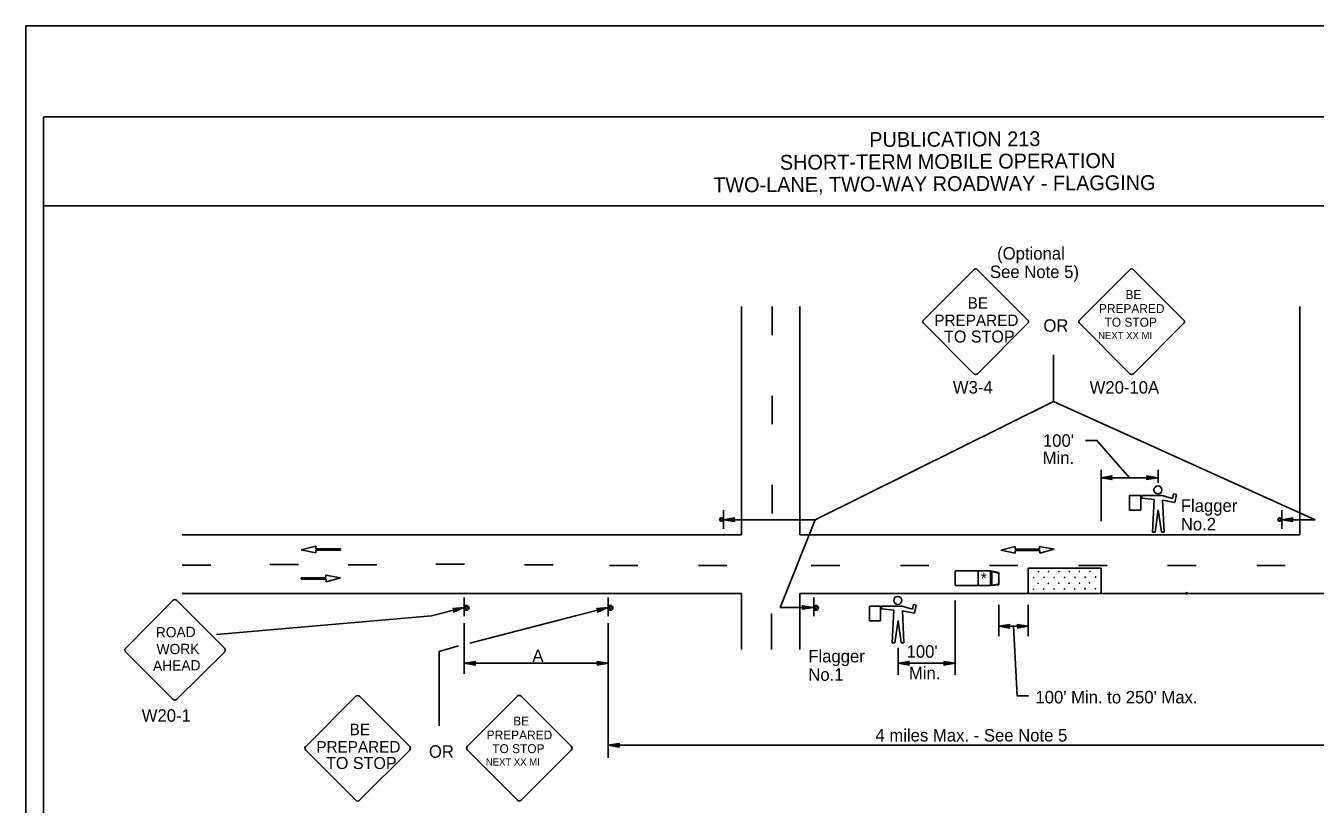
# Model space of a CAD drawing. Extents: x -14145 to -13662, y 30244 to 30661.
# Drawn here: x -13926.17 to -13904.46, y 30464.2 to 30477.31 of the extents above; entities that cross this region are included whole.
import ezdxf

# ---------------------------------------------------------------- set-up
doc = ezdxf.new("R2010")
doc.units = 0
for name, color, linetype in [('1', 7, 'Continuous'), ('10', 7, 'Continuous'), ('2', 7, 'Continuous'), ('4', 7, 'Continuous'), ('61', 7, 'Continuous')]:
    doc.layers.add(name, color=color, linetype=linetype)

msp = doc.modelspace()

# ---------------------------------------------------------------- linework, layer by layer
at = {"layer": '1'}
for p, q in [((-13914.122, 30468.737), (-13914.122, 30472.58)), ((-13913.606, 30472.58), (-13913.606, 30472.1)), ((-13913.138, 30468.737), (-13913.138, 30472.58)), ((-13904.722, 30468.737), (-13904.722, 30472.58)), ((-13908.87, 30471.769), (-13908.87, 30470.985)), ((-13913.606, 30471.08), (-13913.606, 30470.6)), ((-13912.882, 30468.993), (-13908.87, 30470.985)), ((-13904.461, 30468.993), (-13908.87, 30470.985)), ((-13908.068, 30468.97), (-13908.068, 30469.83)), ((-13907.108, 30469.611), (-13907.108, 30469.83)), ((-13908.068, 30469.7), (-13907.108, 30469.7)), ((-13913.606, 30469.58), (-13913.606, 30469.1)), ((-13907.399, 30469.401), (-13907.587, 30469.401)), ((-13907.587, 30469.401), (-13907.587, 30469.151)), ((-13907.399, 30469.151), (-13907.399, 30469.401)), ((-13907.041, 30469.401), (-13907.381, 30469.401)), ((-13907.381, 30469.401), (-13907.381, 30469.357)), ((-13906.863, 30469.349), (-13907.041, 30469.401)), ((-13906.845, 30469.429), (-13906.863, 30469.349)), ((-13906.797, 30469.417), (-13906.845, 30469.429)), ((-13906.827, 30469.283), (-13906.797, 30469.417)), ((-13907.381, 30469.357), (-13907.175, 30469.331)), ((-13907.175, 30469.331), (-13907.203, 30468.785)), ((-13907.006, 30468.785), (-13907.032, 30469.321)), ((-13907.032, 30469.321), (-13906.827, 30469.283)), ((-13914.424, 30469.155), (-13914.424, 30468.837)), ((-13912.882, 30468.993), (-13914.424, 30468.993)), ((-13913.473, 30467.515), (-13912.882, 30468.993)), ((-13907.587, 30469.151), (-13907.399, 30469.151)), ((-13907.158, 30468.785), (-13907.104, 30469.159)), ((-13907.104, 30469.159), (-13907.051, 30468.785)), ((-13905.024, 30469.155), (-13905.024, 30468.837)), ((-13904.461, 30468.993), (-13905.024, 30468.993)), ((-13907.203, 30468.785), (-13907.158, 30468.785)), ((-13907.051, 30468.785), (-13907.006, 30468.785)), ((-13923.54, 30468.737), (-13914.122, 30468.737)), ((-13921.292, 30468.549), (-13921.534, 30468.483)), ((-13921.292, 30468.504), (-13921.292, 30468.549)), ((-13913.138, 30468.737), (-13904.722, 30468.737)), ((-13909.516, 30468.544), (-13909.757, 30468.478)), ((-13909.516, 30468.499), (-13909.516, 30468.544)), ((-13908.858, 30468.498), (-13909.102, 30468.544)), ((-13909.102, 30468.544), (-13909.102, 30468.499)), ((-13921.534, 30468.483), (-13921.29, 30468.436)), ((-13920.876, 30468.504), (-13921.292, 30468.504)), ((-13921.29, 30468.436), (-13921.29, 30468.482)), ((-13921.29, 30468.482), (-13920.876, 30468.482)), ((-13920.876, 30468.482), (-13920.876, 30468.504)), ((-13909.757, 30468.478), (-13909.513, 30468.432)), ((-13909.102, 30468.499), (-13909.516, 30468.499)), ((-13909.513, 30468.477), (-13909.099, 30468.477)), ((-13909.513, 30468.432), (-13909.513, 30468.477)), ((-13909.099, 30468.432), (-13908.858, 30468.498)), ((-13909.099, 30468.477), (-13909.099, 30468.432)), ((-13923.06, 30468.227), (-13923.54, 30468.227)), ((-13921.584, 30468.239), (-13922.064, 30468.239)), ((-13920.264, 30468.233), (-13920.744, 30468.233)), ((-13918.788, 30468.245), (-13919.268, 30468.245)), ((-13917.294, 30468.233), (-13917.774, 30468.233)), ((-13915.866, 30468.221), (-13916.346, 30468.221)), ((-13914.366, 30468.221), (-13914.846, 30468.221)), ((-13912.466, 30468.221), (-13912.946, 30468.221)), ((-13910.966, 30468.221), (-13911.446, 30468.221)), ((-13910.522, 30467.885), (-13910.522, 30468.131)), ((-13909.928, 30468.131), (-13910.522, 30468.131)), ((-13910.138, 30467.885), (-13910.138, 30468.131)), ((-13909.466, 30468.221), (-13909.946, 30468.221)), ((-13909.928, 30467.885), (-13909.928, 30468.131)), ((-13909.928, 30468.131), (-13909.79, 30468.107)), ((-13909.904, 30468.125), (-13909.79, 30468.089)), ((-13909.904, 30467.885), (-13909.904, 30468.125)), ((-13909.79, 30467.897), (-13909.79, 30468.107)), ((-13908.068, 30468.179), (-13909.292, 30468.179)), ((-13909.292, 30467.753), (-13909.292, 30468.179)), ((-13907.966, 30468.221), (-13908.446, 30468.221)), ((-13908.068, 30467.753), (-13908.068, 30468.179)), ((-13906.466, 30468.221), (-13906.946, 30468.221)), ((-13904.966, 30468.221), (-13905.446, 30468.221)), ((-13921.12, 30468.013), (-13921.534, 30468.013)), ((-13921.534, 30468.013), (-13921.534, 30467.991)), ((-13921.534, 30467.991), (-13921.117, 30467.991)), ((-13920.876, 30468.012), (-13921.12, 30468.058)), ((-13921.12, 30468.058), (-13921.12, 30468.013)), ((-13921.117, 30467.946), (-13920.876, 30468.012)), ((-13921.117, 30467.991), (-13921.117, 30467.946)), ((-13909.928, 30467.885), (-13910.522, 30467.885)), ((-13909.928, 30467.885), (-13909.79, 30467.897)), ((-13909.904, 30467.885), (-13909.79, 30467.915)), ((-13923.54, 30467.753), (-13914.122, 30467.753)), ((-13918.79, 30467.682), (-13918.79, 30467.37)), ((-13916.366, 30467.682), (-13916.366, 30467.37)), ((-13914.122, 30466.808), (-13914.122, 30467.753)), ((-13913.138, 30466.808), (-13913.138, 30467.753)), ((-13913.138, 30467.753), (-13897.552, 30467.753)), ((-13912.903, 30467.682), (-13912.903, 30467.37)), ((-13923.696, 30467.635), (-13924.491, 30466.832)), ((-13922.827, 30466.832), (-13923.63, 30467.635)), ((-13919.343, 30467.375), (-13918.796, 30467.515)), ((-13916.919, 30467.375), (-13916.372, 30467.515)), ((-13913.473, 30467.515), (-13912.909, 30467.515)), ((-13911.78, 30467.539), (-13911.968, 30467.539)), ((-13911.968, 30467.539), (-13911.968, 30467.289)), ((-13911.78, 30467.289), (-13911.78, 30467.539)), ((-13911.422, 30467.539), (-13911.762, 30467.539)), ((-13911.762, 30467.539), (-13911.762, 30467.495)), ((-13911.762, 30467.495), (-13911.556, 30467.469)), ((-13911.556, 30467.469), (-13911.584, 30466.923)), ((-13911.244, 30467.487), (-13911.422, 30467.539)), ((-13911.387, 30466.923), (-13911.413, 30467.459)), ((-13911.413, 30467.459), (-13911.208, 30467.421)), ((-13911.226, 30467.567), (-13911.244, 30467.487)), ((-13911.178, 30467.555), (-13911.226, 30467.567)), ((-13911.208, 30467.421), (-13911.178, 30467.555)), ((-13910.522, 30466.379), (-13910.522, 30467.635)), ((-13909.79, 30467.03), (-13909.79, 30467.559)), ((-13909.292, 30467.03), (-13909.292, 30467.559)), ((-13922.961, 30467.058), (-13919.343, 30467.375)), ((-13918.79, 30466.397), (-13918.79, 30467.253)), ((-13918.697, 30466.912), (-13916.919, 30467.375)), ((-13916.366, 30464.985), (-13916.366, 30467.253)), ((-13913.618, 30467.413), (-13913.618, 30466.808)), ((-13911.968, 30467.289), (-13911.78, 30467.289)), ((-13911.539, 30466.923), (-13911.485, 30467.297)), ((-13911.485, 30467.297), (-13911.432, 30466.923)), ((-13909.292, 30467.199), (-13909.79, 30467.199)), ((-13919.21, 30466.774), (-13918.887, 30466.868)), ((-13911.584, 30466.923), (-13911.539, 30466.923)), ((-13911.482, 30466.379), (-13911.482, 30466.834)), ((-13911.432, 30466.923), (-13911.387, 30466.923)), ((-13924.491, 30466.766), (-13923.696, 30465.971)), ((-13923.63, 30465.971), (-13922.827, 30466.766)), ((-13919.21, 30465.522), (-13919.21, 30466.774)), ((-13916.366, 30466.577), (-13918.79, 30466.577)), ((-13911.482, 30466.577), (-13910.522, 30466.577)), ((-13902.224, 30465.195), (-13916.366, 30465.195))]:
    msp.add_line(p, q, dxfattribs=at)
for points in [[(-13911.053, 30472.358), (-13910.212, 30473.2)], [(-13910.146, 30473.2), (-13909.304, 30472.358)], [(-13908.427, 30472.358), (-13907.585, 30473.2)], [(-13907.52, 30473.2), (-13906.677, 30472.358)], [(-13910.212, 30471.45), (-13911.053, 30472.293)], [(-13909.304, 30472.293), (-13910.146, 30471.45)], [(-13907.585, 30471.45), (-13908.427, 30472.293)], [(-13906.677, 30472.293), (-13907.52, 30471.45)], [(-13908.33, 30470.327), (-13908.138, 30470.327), (-13907.588, 30469.7)], [(-13907.894, 30469.676), (-13907.9, 30469.694), (-13908.068, 30469.7), (-13907.894, 30469.676), (-13907.882, 30469.67), (-13908.068, 30469.7), (-13907.9, 30469.712), (-13907.894, 30469.724), (-13908.068, 30469.7), (-13907.882, 30469.73), (-13907.894, 30469.724)], [(-13907.288, 30469.724), (-13907.282, 30469.712), (-13907.108, 30469.7), (-13907.288, 30469.724), (-13907.3, 30469.73), (-13907.108, 30469.7), (-13907.282, 30469.694), (-13907.288, 30469.682), (-13907.108, 30469.7), (-13907.3, 30469.67), (-13907.288, 30469.682)], [(-13914.244, 30468.969), (-13914.25, 30468.981), (-13914.424, 30468.993), (-13914.244, 30468.969), (-13914.238, 30468.963), (-13914.424, 30468.993), (-13914.25, 30468.999), (-13914.244, 30469.011), (-13914.424, 30468.993), (-13914.238, 30469.023), (-13914.244, 30469.011)], [(-13904.844, 30468.969), (-13904.85, 30468.981), (-13905.024, 30468.993), (-13904.844, 30468.969), (-13904.838, 30468.963), (-13905.024, 30468.993), (-13904.85, 30468.999), (-13904.844, 30469.011), (-13905.024, 30468.993), (-13904.838, 30469.023), (-13904.844, 30469.011)], [(-13918.976, 30467.491), (-13918.964, 30467.479), (-13918.796, 30467.515), (-13918.976, 30467.491), (-13918.982, 30467.497), (-13918.796, 30467.515), (-13918.958, 30467.461), (-13918.964, 30467.449), (-13918.796, 30467.515), (-13918.97, 30467.437), (-13918.964, 30467.449)], [(-13916.552, 30467.491), (-13916.54, 30467.479), (-13916.372, 30467.515), (-13916.552, 30467.491), (-13916.558, 30467.497), (-13916.372, 30467.515), (-13916.534, 30467.461), (-13916.54, 30467.449), (-13916.372, 30467.515), (-13916.546, 30467.437), (-13916.54, 30467.449)], [(-13913.089, 30467.539), (-13913.083, 30467.527), (-13912.909, 30467.515), (-13913.089, 30467.539), (-13913.095, 30467.545), (-13912.909, 30467.515), (-13913.083, 30467.509), (-13913.089, 30467.497), (-13912.909, 30467.515), (-13913.095, 30467.485), (-13913.089, 30467.497)], [(-13909.61, 30467.175), (-13909.616, 30467.187), (-13909.79, 30467.199), (-13909.61, 30467.175), (-13909.604, 30467.169), (-13909.79, 30467.199), (-13909.616, 30467.205), (-13909.61, 30467.217), (-13909.79, 30467.199), (-13909.604, 30467.229), (-13909.61, 30467.217)], [(-13909.472, 30467.223), (-13909.466, 30467.205), (-13909.292, 30467.199), (-13909.472, 30467.223), (-13909.478, 30467.229), (-13909.292, 30467.199), (-13909.466, 30467.193), (-13909.472, 30467.175), (-13909.292, 30467.199), (-13909.478, 30467.169), (-13909.472, 30467.175)], [(-13909.287, 30466.027), (-13909.479, 30466.027), (-13909.541, 30467.199)], [(-13918.61, 30466.559), (-13918.616, 30466.571), (-13918.79, 30466.577), (-13918.61, 30466.559), (-13918.604, 30466.547), (-13918.79, 30466.577), (-13918.616, 30466.589), (-13918.61, 30466.601), (-13918.79, 30466.577), (-13918.604, 30466.607), (-13918.61, 30466.601)], [(-13916.546, 30466.601), (-13916.534, 30466.583), (-13916.366, 30466.577), (-13916.546, 30466.601), (-13916.552, 30466.607), (-13916.366, 30466.577), (-13916.534, 30466.565), (-13916.546, 30466.553), (-13916.366, 30466.577), (-13916.552, 30466.547), (-13916.546, 30466.553)], [(-13911.308, 30466.553), (-13911.314, 30466.571), (-13911.482, 30466.577), (-13911.308, 30466.553), (-13911.296, 30466.547), (-13911.482, 30466.577), (-13911.314, 30466.589), (-13911.308, 30466.601), (-13911.482, 30466.577), (-13911.296, 30466.607), (-13911.308, 30466.601)], [(-13910.702, 30466.601), (-13910.696, 30466.589), (-13910.522, 30466.577), (-13910.702, 30466.601), (-13910.714, 30466.607), (-13910.522, 30466.577), (-13910.696, 30466.571), (-13910.702, 30466.559), (-13910.522, 30466.577), (-13910.714, 30466.547), (-13910.702, 30466.559)], [(-13921.459, 30465.178), (-13920.617, 30466.02)], [(-13920.552, 30466.02), (-13919.709, 30465.178)], [(-13918.738, 30465.18), (-13917.896, 30466.022)], [(-13917.831, 30466.022), (-13916.988, 30465.18)], [(-13920.617, 30464.271), (-13921.459, 30465.113)], [(-13919.709, 30465.113), (-13920.552, 30464.27)], [(-13917.896, 30464.272), (-13918.738, 30465.115)], [(-13916.988, 30465.115), (-13917.831, 30464.272)], [(-13916.186, 30465.177), (-13916.192, 30465.189), (-13916.366, 30465.195), (-13916.186, 30465.177), (-13916.18, 30465.165), (-13916.366, 30465.195), (-13916.192, 30465.207), (-13916.186, 30465.219), (-13916.366, 30465.195), (-13916.18, 30465.225), (-13916.186, 30465.219)]]:
    msp.add_lwpolyline(points, dxfattribs=at)
for centre, radius in [((-13907.109, 30469.495), 0.0672), ((-13914.46, 30468.997), 0.0298), ((-13905.06, 30468.997), 0.0298), ((-13909.122, 30468.118), 0.00272), ((-13908.949, 30468.119), 0.00272), ((-13908.775, 30468.12), 0.00272), ((-13908.6, 30468.119), 0.00272), ((-13908.429, 30468.121), 0.00272), ((-13908.254, 30468.124), 0.00272), ((-13909.201, 30468.02), 0.00272), ((-13909.127, 30467.922), 0.00272), ((-13909.027, 30468.022), 0.00272), ((-13908.955, 30467.922), 0.00272), ((-13908.855, 30468.02), 0.00272), ((-13908.779, 30467.923), 0.00272), ((-13908.679, 30468.022), 0.00272), ((-13908.606, 30467.923), 0.00272), ((-13908.506, 30468.021), 0.00272), ((-13908.43, 30467.924), 0.00272), ((-13908.334, 30468.026), 0.00272), ((-13908.332, 30468.023), 0.00272), ((-13908.259, 30467.928), 0.00272), ((-13908.159, 30468.028), 0.00272), ((-13911.49, 30467.634), 0.0672), ((-13909.207, 30467.824), 0.00272), ((-13909.032, 30467.826), 0.00272), ((-13908.859, 30467.825), 0.00272), ((-13908.685, 30467.827), 0.00272), ((-13908.511, 30467.828), 0.00272), ((-13908.339, 30467.831), 0.00272), ((-13908.337, 30467.828), 0.00272), ((-13908.164, 30467.832), 0.00272), ((-13906.625, 30467.754), 0.012), ((-13918.751, 30467.51), 0.0408), ((-13916.327, 30467.51), 0.0408), ((-13912.864, 30467.51), 0.0408)]:
    msp.add_circle(centre, radius, dxfattribs=at)
for centre, radius, start, end in [((-13910.179, 30473.167), 0.0465, 45.0316, 135), ((-13907.552, 30473.167), 0.0465, 45.0316, 135), ((-13911.02, 30472.326), 0.0465, 135, 224.9684), ((-13909.337, 30472.326), 0.0465, 315, 45.0316), ((-13908.394, 30472.326), 0.0465, 135, 224.9684), ((-13906.71, 30472.326), 0.0465, 315, 45.0316), ((-13910.179, 30471.483), 0.0465, 224.9684, 315), ((-13907.552, 30471.483), 0.0465, 224.9684, 315), ((-13914.459, 30468.998), 0.0214, 355.7499, 350.479), ((-13905.059, 30468.998), 0.0214, 355.7499, 350.479), ((-13923.663, 30467.602), 0.0465, 45, 135), ((-13918.756, 30467.517), 0.0214, 189.521, 184.2501), ((-13916.332, 30467.517), 0.0214, 189.521, 184.2501), ((-13912.869, 30467.517), 0.0214, 189.521, 184.2501), ((-13924.458, 30466.8), 0.0465, 135, 225), ((-13922.86, 30466.799), 0.0465, 315, 45), ((-13923.663, 30466.004), 0.0465, 225, 315), ((-13920.585, 30465.987), 0.0465, 45.0316, 135), ((-13917.864, 30465.989), 0.0465, 45.0316, 135), ((-13921.426, 30465.146), 0.0465, 135, 224.9684), ((-13919.742, 30465.146), 0.0465, 315, 45.0316), ((-13918.705, 30465.147), 0.0465, 135, 224.9684), ((-13917.021, 30465.147), 0.0465, 315, 45.0316), ((-13920.585, 30464.303), 0.0465, 224.9684, 315), ((-13917.864, 30464.305), 0.0465, 224.9684, 315)]:
    msp.add_arc(centre, radius, start, end, dxfattribs=at)
at = {"layer": '10'}
for p, q in [((-13925.874, 30475.777), (-13894.422, 30475.777)), ((-13925.874, 30453.207), (-13925.874, 30475.777)), ((-13925.874, 30474.277), (-13894.422, 30474.277))]:
    msp.add_line(p, q, dxfattribs=at)
at = {"layer": '61'}
msp.add_lwpolyline([(-13926.174, 30477.307), (-13893.174, 30477.307), (-13893.174, 30451.807), (-13926.174, 30451.807)], close=True, dxfattribs=at)

# ---------------------------------------------------------------- texts
at = {"layer": '1'}
for s, height, p in [('BE', 0.1925, (-13910.314, 30472.545)), ('BE', 0.15, (-13907.655, 30472.707)), ('PREPARED', 0.1925, (-13910.875, 30472.253)), ('PREPARED', 0.15, (-13908.102, 30472.472)), ('TO STOP', 0.15, (-13908.008, 30472.242)), ('TO STOP', 0.2024, (-13910.711, 30471.975)), ('NEXT XX MI', 0.12, (-13908.116, 30472.033)), ('BE', 0.1925, (-13920.72, 30465.366)), ('BE', 0.15, (-13917.966, 30465.529)), ('PREPARED', 0.15, (-13918.413, 30465.294)), ('PREPARED', 0.1925, (-13921.281, 30465.074)), ('TO STOP', 0.15, (-13918.319, 30465.064)), ('TO STOP', 0.2024, (-13921.117, 30464.796)), ('NEXT XX MI', 0.12, (-13918.427, 30464.855))]:
    msp.add_text(s, height=height, dxfattribs=at).set_placement(p)
for s, height, rotation, p in [('*', 0.198, 0.7233, (-13910.092, 30467.904)), ('ROAD', 0.1735, 0.7566, (-13923.983, 30467.01)), ('WORK', 0.1733, 0.7588, (-13923.97, 30466.725)), ('AHEAD', 0.1735, 0.7481, (-13924.03, 30466.447))]:
    msp.add_text(s, height=height, rotation=rotation, dxfattribs=at).set_placement(p)
at = {"layer": '2'}
for s, p in [('(Optional', (-13909.817, 30473.371)), ('See Note 5)', (-13909.938, 30473.061)), ('OR', (-13909.038, 30472.156)), ('W3-4', (-13910.563, 30471.117)), ('W20-10A', (-13908.26, 30471.116)), ("100'", (-13909.046, 30470.22)), ('Min.', (-13909.05, 30469.93)), ('Flagger', (-13906.724, 30469.124)), ('No.2', (-13906.724, 30468.814)), ('A', (-13917.643, 30466.598)), ('Flagger', (-13912.997, 30466.591)), ("100'", (-13911.342, 30466.67)), ('No.1', (-13912.997, 30466.281)), ('Min.', (-13911.303, 30466.307)), ("100' Min. to 250' Max.", (-13909.172, 30465.901)), ('W20-1', (-13924.221, 30465.592)), ('4 miles Max. - See Note 5', (-13911.866, 30465.259)), ('OR', (-13919.385, 30464.986))]:
    msp.add_text(s, height=0.21, dxfattribs=at).set_placement(p)
at = {"layer": '4'}
for s, p in [('PUBLICATION 213', (-13911.969, 30475.266)), ('SHORT-TERM MOBILE OPERATION', (-13913.475, 30474.883)), ('TWO-LANE, TWO-WAY ROADWAY - FLAGGING', (-13914.597, 30474.503))]:
    msp.add_text(s, height=0.25, rotation=0.31, dxfattribs=at).set_placement(p)

doc.saveas('drawing.dxf')
